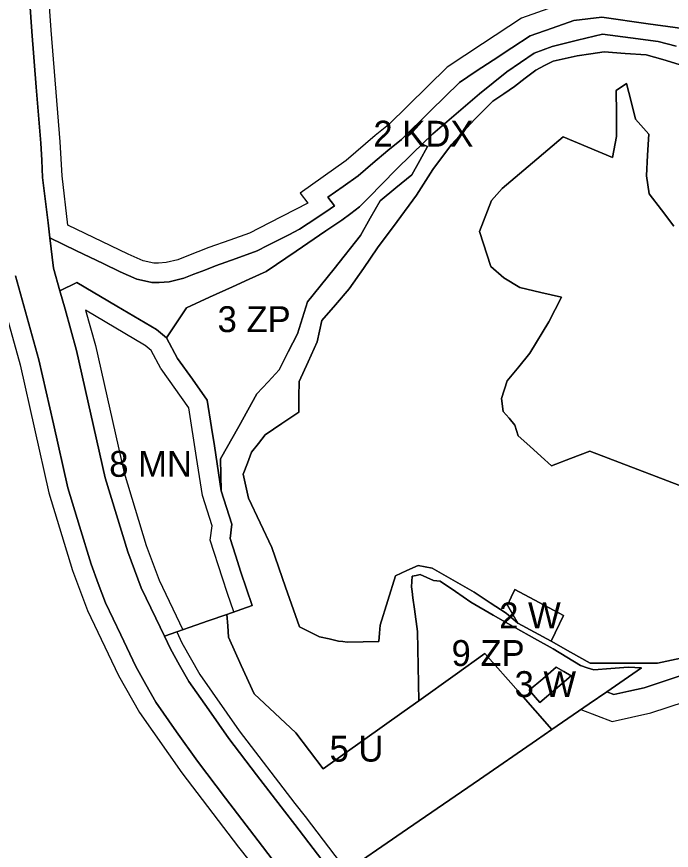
# Model space of a CAD drawing. Extents: x 7423691 to 7425475, y 5552085 to 5554331.
# Drawn here: x 7424385.3 to 7424587.5, y 5552663.9 to 5552921.5 of the extents above; entities that cross this region are included whole.
import ezdxf

# ---------------------------------------------------------------- set-up
doc = ezdxf.new("R2010")
doc.units = 0
for name, color, linetype in [('linia_zabudowy_nieprzekraczalna', 7, 'Continuous'), ('linie_rozgraniczajace', 7, 'Continuous'), ('oznaczenia_przeznaczen', 7, 'Continuous')]:
    doc.layers.add(name, color=color, linetype=linetype)

msp = doc.modelspace()

# ---------------------------------------------------------------- linework, layer by layer
at = {"layer": 'linia_zabudowy_nieprzekraczalna'}
for points in [[(7424556.1, 5552926.21), (7424541.26, 5552921.01), (7424529.19, 5552913.06), (7424518.25, 5552905.86), (7424500.12, 5552888.01), (7424496.07, 5552884.73), (7424487.09, 5552877.03), (7424472.85, 5552866.99), (7424475.26, 5552863.86), (7424463.35, 5552857.78), (7424457.15, 5552854.61), (7424451.09, 5552852.44), (7424444.67, 5552850.15), (7424437.81, 5552847.48), (7424435.04, 5552846.37), (7424431.41, 5552845.48), (7424429.06, 5552845.31), (7424427.69, 5552845.31), (7424424.32, 5552846.06), (7424419.75, 5552848.13), (7424401.1, 5552857.09), (7424399.27, 5552872.34), (7424398.71, 5552882.81), (7424395.91, 5552917.33), (7424395.1, 5552928.99)], [(7424378.95, 5552840.23), (7424386.33, 5552813.96), (7424395.24, 5552774.37), (7424402.55, 5552750.36), (7424407.19, 5552738.02), (7424416.77, 5552717.96), (7424423.18, 5552706.49), (7424436.27, 5552687.89), (7424453.78, 5552664.96), (7424456.99, 5552660.89), (7424481.21, 5552628.98), (7424487.16, 5552620.28), (7424504.05, 5552598.12), (7424504.53, 5552597.51), (7424504.36, 5552596.69), (7424479.58, 5552583.13), (7424397.48, 5552551.4), (7424333.75, 5552516.27)], [(7424452.41, 5552737.59), (7424450.45, 5552743.26), (7424448.87, 5552747.97), (7424445.05, 5552759.75), (7424445.63, 5552764.16), (7424442.63, 5552773.57), (7424440.82, 5552785.33), (7424438.46, 5552800.64), (7424429.89, 5552812.67), (7424429.82, 5552812.77), (7424426.81, 5552818.34), (7424426.79, 5552818.37), (7424424.99, 5552819.89), (7424424.97, 5552819.91), (7424424.8, 5552820.01), (7424406.53, 5552830.8), (7424409.61, 5552819.84), (7424418.46, 5552780.51), (7424425.28, 5552758.09), (7424429.29, 5552747.43), (7424436.6, 5552732.11)], [(7424434.7, 5552731.45), (7424436.32, 5552728.07), (7424441.82, 5552718.22), (7424454.01, 5552700.91), (7424471.16, 5552678.45), (7424474.39, 5552674.35), (7424487.13, 5552657.57)], [(7424559.55, 5552707.41), (7424569.21, 5552703.73), (7424581.21, 5552706.46), (7424602.66, 5552713.4), (7424603.78, 5552713.38), (7424612.4, 5552698.46), (7424624.81, 5552691.11), (7424646.93, 5552681.85), (7424649.5, 5552679.77), (7424651.53, 5552677.14), (7424652.42, 5552674.73), (7424652.99, 5552668.07), (7424648.05, 5552663.36)]]:
    msp.add_lwpolyline(points, dxfattribs=at)
at = {"layer": 'linie_rozgraniczajace'}
for points in [[(7424594.74, 5552917.28), (7424580.39, 5552919.29), (7424566.03, 5552921.29), (7424561.74, 5552920.81), (7424557.44, 5552920.32), (7424550.69, 5552917.96), (7424543.94, 5552915.59), (7424538.22, 5552911.82), (7424532.49, 5552908.05), (7424527.27, 5552904.61), (7424522.04, 5552901.17), (7424513.08, 5552892.35), (7424504.12, 5552883.53), (7424499.91, 5552880.12), (7424495.34, 5552876.21), (7424490.78, 5552872.29), (7424486.1, 5552869), (7424481.43, 5552865.7), (7424483.48, 5552863.05), (7424480.76, 5552861.23), (7424475.34, 5552857.6), (7424472.62, 5552855.78), (7424469.35, 5552854.1), (7424466.08, 5552852.43), (7424462.81, 5552850.76), (7424459.53, 5552849.09), (7424453.11, 5552846.79), (7424446.69, 5552844.5), (7424443.35, 5552843.19), (7424440.01, 5552841.89), (7424436.88, 5552840.65), (7424432.35, 5552839.53), (7424429.27, 5552839.31), (7424427.03, 5552839.31), (7424424.72, 5552839.83), (7424422.41, 5552840.34), (7424419.84, 5552841.5), (7424417.27, 5552842.66), (7424411.95, 5552845.22), (7424403.74, 5552849.17), (7424395.54, 5552853.11), (7424394.97, 5552857.79), (7424393.29, 5552871.83), (7424393.01, 5552877.12), (7424392.73, 5552882.41), (7424391.33, 5552899.64), (7424389.92, 5552916.88), (7424389.1, 5552928.86)], [(7424389.1, 5552928.86), (7424389.92, 5552916.88), (7424391.33, 5552899.64), (7424392.73, 5552882.41), (7424393.01, 5552877.12), (7424393.29, 5552871.83), (7424394.97, 5552857.79), (7424395.54, 5552853.11), (7424396.66, 5552843.76), (7424398.61, 5552836.8), (7424400.22, 5552831.07), (7424403.79, 5552818.37), (7424408.22, 5552798.67), (7424412.65, 5552778.98), (7424416.12, 5552767.57), (7424419.6, 5552756.16), (7424421.68, 5552750.62), (7424423.77, 5552745.08), (7424428.27, 5552735.65), (7424430.9, 5552730.13), (7424432.76, 5552726.23), (7424435.6, 5552721.16), (7424438.43, 5552716.08), (7424444.61, 5552707.31), (7424450.79, 5552698.54), (7424459.4, 5552687.27), (7424468, 5552676), (7424471.23, 5552671.9), (7424483.83, 5552655.3)], [(7424589, 5552912.34), (7424583.44, 5552913.81), (7424574.86, 5552914.96), (7424566.29, 5552916.1), (7424558.5, 5552914.16), (7424550.71, 5552912.21), (7424547.94, 5552911.23), (7424545.17, 5552910.24), (7424540.93, 5552907.32), (7424536.69, 5552904.41), (7424532.45, 5552901.04), (7424528.22, 5552897.67), (7424521.03, 5552891.5), (7424513.84, 5552885.32), (7424510.56, 5552882.1), (7424507.88, 5552879.48), (7424501.93, 5552873.65), (7424498.85, 5552870.47), (7424493.49, 5552865.01), (7424491.19, 5552862.72), (7424488.48, 5552860.64), (7424485.77, 5552858.57), (7424480.83, 5552855.26), (7424471.59, 5552848.98), (7424462.35, 5552842.7), (7424457.13, 5552840.34), (7424451.92, 5552837.98), (7424444.84, 5552834.77), (7424437.76, 5552831.56), (7424434.65, 5552826.89), (7424431.53, 5552822.21), (7424428.47, 5552824.81), (7424416.16, 5552832.08), (7424403.85, 5552839.35), (7424398.61, 5552836.8), (7424396.66, 5552843.76), (7424395.54, 5552853.11), (7424403.74, 5552849.17), (7424411.95, 5552845.22), (7424417.27, 5552842.66), (7424419.84, 5552841.5), (7424422.41, 5552840.34), (7424424.72, 5552839.83), (7424427.03, 5552839.31), (7424429.27, 5552839.31), (7424432.35, 5552839.53), (7424436.88, 5552840.65), (7424440.01, 5552841.89), (7424443.35, 5552843.19), (7424446.69, 5552844.5), (7424453.11, 5552846.79), (7424459.53, 5552849.09), (7424462.81, 5552850.76), (7424466.08, 5552852.43), (7424469.35, 5552854.1), (7424472.62, 5552855.78), (7424475.34, 5552857.6), (7424480.76, 5552861.23), (7424483.48, 5552863.05), (7424481.43, 5552865.7), (7424486.1, 5552869), (7424490.78, 5552872.29), (7424495.34, 5552876.21), (7424499.91, 5552880.12), (7424504.12, 5552883.53), (7424513.08, 5552892.35), (7424522.04, 5552901.17), (7424527.27, 5552904.61), (7424532.49, 5552908.05), (7424538.22, 5552911.82), (7424543.94, 5552915.59), (7424550.69, 5552917.96), (7424557.44, 5552920.32), (7424561.74, 5552920.81), (7424566.03, 5552921.29), (7424580.39, 5552919.29), (7424594.74, 5552917.28)], [(7424448.49, 5552774.95), (7424448.28, 5552784.84), (7424453.89, 5552794.92), (7424459.5, 5552805), (7424462.95, 5552808.69), (7424466.39, 5552812.38), (7424469.19, 5552817.95), (7424471.99, 5552823.52), (7424473.56, 5552828.45), (7424475.13, 5552833.39), (7424483.32, 5552843.62), (7424491.51, 5552853.86), (7424494.53, 5552859.2), (7424497.56, 5552864.54), (7424502.45, 5552868.6), (7424507.34, 5552872.66), (7424509.78, 5552877.03), (7424512.23, 5552881.4), (7424510.56, 5552882.1), (7424513.84, 5552885.32), (7424521.03, 5552891.5), (7424528.22, 5552897.67), (7424532.45, 5552901.04), (7424536.69, 5552904.41), (7424540.93, 5552907.32), (7424545.17, 5552910.24), (7424547.94, 5552911.23), (7424550.71, 5552912.21), (7424558.5, 5552914.16), (7424566.29, 5552916.1), (7424574.86, 5552914.96), (7424583.44, 5552913.81), (7424589, 5552912.34)], [(7424455.2, 5552780.11), (7424456.53, 5552783.5), (7424457.86, 5552786.89), (7424459.94, 5552789.58), (7424462.02, 5552792.26), (7424467.21, 5552795.78), (7424472.39, 5552799.29), (7424472.47, 5552804.02), (7424472.54, 5552808.75), (7424475.32, 5552814.87), (7424478.11, 5552821), (7424478.83, 5552824.32), (7424479.56, 5552827.64), (7424483.78, 5552832.5), (7424488, 5552837.37), (7424492.39, 5552843.72), (7424496.78, 5552850.07), (7424502.79, 5552858.2), (7424508.79, 5552866.33), (7424513.84, 5552874.24), (7424519.57, 5552882.02), (7424523.2, 5552885.89), (7424526.84, 5552889.76), (7424529.63, 5552892.56), (7424532.43, 5552895.35), (7424535.73, 5552897.64), (7424539.03, 5552899.93), (7424542.34, 5552902.43), (7424545.65, 5552904.93), (7424548.35, 5552906.35), (7424551.06, 5552907.77), (7424554.76, 5552908.54), (7424558.46, 5552909.32), (7424562.61, 5552909.94), (7424566.75, 5552910.56), (7424573.28, 5552910.13), (7424579.8, 5552909.69), (7424584.89, 5552908.19), (7424589.98, 5552906.68)], [(7424589.98, 5552906.68), (7424584.89, 5552908.19), (7424579.8, 5552909.69), (7424573.28, 5552910.13), (7424566.75, 5552910.56), (7424562.61, 5552909.94), (7424558.46, 5552909.32), (7424554.76, 5552908.54), (7424551.06, 5552907.77), (7424548.35, 5552906.35), (7424545.65, 5552904.93), (7424542.34, 5552902.43), (7424539.03, 5552899.93), (7424535.73, 5552897.64), (7424532.43, 5552895.35), (7424529.63, 5552892.56), (7424526.84, 5552889.76), (7424523.2, 5552885.89), (7424519.57, 5552882.02), (7424513.84, 5552874.24), (7424508.79, 5552866.33), (7424502.79, 5552858.2), (7424496.78, 5552850.07), (7424492.39, 5552843.72), (7424488, 5552837.37), (7424483.78, 5552832.5), (7424479.56, 5552827.64), (7424478.83, 5552824.32), (7424478.11, 5552821), (7424475.32, 5552814.87), (7424472.54, 5552808.75), (7424472.47, 5552804.02), (7424472.39, 5552799.29), (7424467.21, 5552795.78), (7424462.02, 5552792.26), (7424459.94, 5552789.58), (7424457.86, 5552786.89), (7424456.53, 5552783.5), (7424455.2, 5552780.11), (7424456.02, 5552776.41), (7424456.85, 5552772.71), (7424460.47, 5552765.09), (7424464.08, 5552757.46), (7424468.37, 5552745.21), (7424472.66, 5552732.95), (7424475.76, 5552731.44), (7424478.86, 5552729.93), (7424481.79, 5552729.24), (7424484.73, 5552728.55), (7424486.04, 5552728.42), (7424487.35, 5552728.29), (7424492.27, 5552728.37), (7424497.19, 5552728.46), (7424497.38, 5552730.99), (7424497.57, 5552733.52), (7424499.95, 5552741.15), (7424502.33, 5552748.78), (7424505.83, 5552750.36), (7424509.33, 5552751.93), (7424511.5, 5552751.53), (7424513.68, 5552751.13), (7424520.12, 5552747.41), (7424526.56, 5552743.69), (7424531.53, 5552740.45), (7424536.5, 5552737.21), (7424540.11, 5552734.12), (7424545.25, 5552731.33), (7424550.37, 5552728.52), (7424556.39, 5552725.13), (7424562.41, 5552721.74), (7424572.85, 5552721.74), (7424583.3, 5552721.73), (7424590.51, 5552723.27)], [(7424588.3, 5552856.8), (7424584.49, 5552861.75), (7424580.67, 5552866.69), (7424579.83, 5552872.26), (7424580.19, 5552878.71), (7424580.55, 5552885.16), (7424576.43, 5552889.79), (7424575.07, 5552895.29), (7424573.7, 5552900.79), (7424570.51, 5552898.62), (7424570.56, 5552891.52), (7424570.62, 5552884.42), (7424569.38, 5552878), (7424561.72, 5552881.16), (7424554.07, 5552884.33), (7424544.65, 5552876.36), (7424535.24, 5552868.38), (7424531.93, 5552864.65), (7424528.24, 5552855.09), (7424531.76, 5552844.32), (7424535.8, 5552840.76), (7424540.75, 5552837.82), (7424547.19, 5552836.3), (7424553.62, 5552834.77), (7424549.73, 5552827.15), (7424543.86, 5552817.56), (7424540.36, 5552813.32), (7424536.8, 5552809.01), (7424535.1, 5552803.51), (7424535.59, 5552799.51), (7424537.38, 5552797.4), (7424539.17, 5552795.3), (7424540.22, 5552792.03), (7424543.77, 5552788.81), (7424547.32, 5552785.59), (7424550.51, 5552782.7), (7424556.42, 5552784.96), (7424562.33, 5552787.23), (7424577.19, 5552781.58), (7424592.05, 5552775.93)], [(7424528.24, 5552855.09), (7424531.93, 5552864.65), (7424535.24, 5552868.38), (7424544.65, 5552876.36), (7424554.07, 5552884.33), (7424561.72, 5552881.16), (7424569.38, 5552878), (7424570.62, 5552884.42), (7424570.56, 5552891.52), (7424570.51, 5552898.62), (7424573.7, 5552900.79), (7424575.07, 5552895.29), (7424576.43, 5552889.79), (7424580.55, 5552885.16), (7424580.19, 5552878.71), (7424579.83, 5552872.26), (7424580.67, 5552866.69), (7424584.49, 5552861.75), (7424588.3, 5552856.8)], [(7424539.17, 5552795.3), (7424537.38, 5552797.4), (7424535.59, 5552799.51), (7424535.1, 5552803.51), (7424536.8, 5552809.01), (7424540.36, 5552813.32), (7424543.86, 5552817.56), (7424549.73, 5552827.15), (7424553.62, 5552834.77), (7424547.19, 5552836.3), (7424540.75, 5552837.82), (7424535.8, 5552840.76), (7424531.76, 5552844.32), (7424528.24, 5552855.09)], [(7424384.86, 5552841.41), (7424388.5, 5552828.42), (7424392.15, 5552815.43), (7424396.6, 5552795.67), (7424401.04, 5552775.91), (7424404.64, 5552764.1), (7424408.23, 5552752.3), (7424410.47, 5552746.33), (7424412.72, 5552740.37), (7424417.41, 5552730.54), (7424422.1, 5552720.71), (7424425.18, 5552715.2), (7424428.26, 5552709.69), (7424434.69, 5552700.56), (7424441.11, 5552691.44), (7424449.82, 5552680.04), (7424458.52, 5552668.64), (7424473.91, 5552648.52)], [(7424473.91, 5552648.52), (7424458.52, 5552668.64), (7424449.82, 5552680.04), (7424441.11, 5552691.44), (7424434.69, 5552700.56), (7424428.26, 5552709.69), (7424425.18, 5552715.2), (7424422.1, 5552720.71), (7424417.41, 5552730.54), (7424412.72, 5552740.37), (7424410.47, 5552746.33), (7424408.23, 5552752.3), (7424404.64, 5552764.1), (7424401.04, 5552775.91), (7424396.6, 5552795.67), (7424392.15, 5552815.43), (7424388.5, 5552828.42), (7424384.86, 5552841.41)], [(7424592.05, 5552775.93), (7424577.19, 5552781.58), (7424562.33, 5552787.23), (7424556.42, 5552784.96), (7424550.51, 5552782.7), (7424547.32, 5552785.59), (7424543.77, 5552788.81), (7424540.22, 5552792.03), (7424539.17, 5552795.3)], [(7424520.12, 5552747.41), (7424513.68, 5552751.13), (7424511.5, 5552751.53), (7424509.33, 5552751.93), (7424505.83, 5552750.36), (7424502.33, 5552748.78), (7424499.95, 5552741.15), (7424497.57, 5552733.52), (7424497.38, 5552730.99), (7424497.19, 5552728.46), (7424492.27, 5552728.37), (7424487.35, 5552728.29), (7424486.04, 5552728.42), (7424484.73, 5552728.55), (7424481.79, 5552729.24), (7424478.86, 5552729.93), (7424475.76, 5552731.44), (7424472.66, 5552732.95), (7424468.37, 5552745.21), (7424464.08, 5552757.46), (7424460.47, 5552765.09), (7424456.85, 5552772.71), (7424456.02, 5552776.41), (7424455.2, 5552780.11)], [(7424451.75, 5552764.71), (7424450.12, 5552769.83), (7424448.49, 5552774.95)], [(7424590.28, 5552717.8), (7424579.09, 5552714.18), (7424574.44, 5552713.12), (7424569.79, 5552712.06), (7424567.56, 5552712.92), (7424578.34, 5552720.33), (7424574.14, 5552720.49), (7424568.85, 5552720.09), (7424563.56, 5552719.7), (7424561.54, 5552720.37), (7424559.51, 5552721.04), (7424555.29, 5552723.6), (7424551.07, 5552726.16), (7424545.25, 5552729.4), (7424539.43, 5552732.65), (7424532.52, 5552736.64), (7424525.61, 5552740.64), (7424520.88, 5552743.87), (7424516.15, 5552747.1), (7424515.1, 5552747.2), (7424514.04, 5552747.3), (7424511.98, 5552748.21), (7424509.92, 5552749.12), (7424508.69, 5552748.88), (7424507.46, 5552748.64), (7424507.35, 5552747), (7424507.23, 5552745.37), (7424507.43, 5552743.89), (7424507.71, 5552741.9), (7424508.18, 5552738.44), (7424509.14, 5552731.51), (7424509.31, 5552720.84), (7424509.48, 5552710.16), (7424504.97, 5552706.95), (7424479.98, 5552689.16), (7424475.72, 5552694.72), (7424471.47, 5552700.27), (7424465.04, 5552706.28), (7424458.61, 5552712.3), (7424454.65, 5552721.03), (7424450.69, 5552729.76), (7424450.46, 5552733.3), (7424450.22, 5552736.84), (7424458.01, 5552739.54), (7424456.29, 5552744.69), (7424454.57, 5552749.85), (7424452.87, 5552755.08), (7424451.18, 5552760.31), (7424451.75, 5552764.71)], [(7424590.51, 5552723.27), (7424583.3, 5552721.73), (7424572.85, 5552721.74), (7424562.41, 5552721.74), (7424556.39, 5552725.13), (7424550.37, 5552728.52), (7424554.2, 5552736.52), (7424546.7, 5552740.51), (7424539.2, 5552744.5), (7424538.04, 5552742.11), (7424536.89, 5552739.71), (7424538.59, 5552736.75), (7424540.11, 5552734.12), (7424536.5, 5552737.21), (7424531.53, 5552740.45), (7424526.56, 5552743.69), (7424520.12, 5552747.41)], [(7424483.83, 5552655.3), (7424506.02, 5552670.56), (7424528.21, 5552685.83), (7424545.9, 5552698.02), (7424550.65, 5552701.28), (7424562.12, 5552709.17), (7424567.56, 5552712.92), (7424569.79, 5552712.06), (7424574.44, 5552713.12), (7424579.09, 5552714.18), (7424590.28, 5552717.8)]]:
    msp.add_lwpolyline(points, dxfattribs=at)
for points in [[(7424431.53, 5552822.21), (7424434.65, 5552826.89), (7424437.76, 5552831.56), (7424444.84, 5552834.77), (7424451.92, 5552837.98), (7424457.13, 5552840.34), (7424462.35, 5552842.7), (7424471.59, 5552848.98), (7424480.83, 5552855.26), (7424485.77, 5552858.57), (7424488.48, 5552860.64), (7424491.19, 5552862.72), (7424493.49, 5552865.01), (7424498.85, 5552870.47), (7424501.93, 5552873.65), (7424507.88, 5552879.48), (7424510.56, 5552882.1), (7424512.23, 5552881.4), (7424509.78, 5552877.03), (7424507.34, 5552872.66), (7424502.45, 5552868.6), (7424497.56, 5552864.54), (7424494.53, 5552859.2), (7424491.51, 5552853.86), (7424483.32, 5552843.62), (7424475.13, 5552833.39), (7424473.56, 5552828.45), (7424471.99, 5552823.52), (7424469.19, 5552817.95), (7424466.39, 5552812.38), (7424462.95, 5552808.69), (7424459.5, 5552805), (7424453.89, 5552794.92), (7424448.28, 5552784.84), (7424448.49, 5552774.95), (7424447.62, 5552780.59), (7424446.35, 5552788.86), (7424445.46, 5552794.6), (7424444.17, 5552802.96), (7424439.56, 5552809.44), (7424434.94, 5552815.92)], [(7424398.61, 5552836.8), (7424403.85, 5552839.35), (7424416.16, 5552832.08), (7424428.47, 5552824.81), (7424431.53, 5552822.21), (7424434.94, 5552815.92), (7424439.56, 5552809.44), (7424444.17, 5552802.96), (7424445.46, 5552794.6), (7424446.35, 5552788.86), (7424447.62, 5552780.59), (7424448.49, 5552774.95), (7424450.12, 5552769.83), (7424451.75, 5552764.71), (7424451.18, 5552760.31), (7424452.87, 5552755.08), (7424454.57, 5552749.85), (7424456.29, 5552744.69), (7424458.01, 5552739.54), (7424450.22, 5552736.84), (7424444.46, 5552734.84), (7424430.9, 5552730.13), (7424428.27, 5552735.65), (7424423.77, 5552745.08), (7424421.68, 5552750.62), (7424419.6, 5552756.16), (7424416.12, 5552767.57), (7424412.65, 5552778.98), (7424408.22, 5552798.67), (7424403.79, 5552818.37), (7424400.22, 5552831.07)], [(7424507.23, 5552745.37), (7424507.35, 5552747), (7424507.46, 5552748.64), (7424508.69, 5552748.88), (7424509.92, 5552749.12), (7424511.98, 5552748.21), (7424514.04, 5552747.3), (7424515.1, 5552747.2), (7424516.15, 5552747.1), (7424520.88, 5552743.87), (7424525.61, 5552740.64), (7424532.52, 5552736.64), (7424539.43, 5552732.65), (7424545.25, 5552729.4), (7424551.07, 5552726.16), (7424555.29, 5552723.6), (7424559.51, 5552721.04), (7424561.54, 5552720.37), (7424563.56, 5552719.7), (7424568.85, 5552720.09), (7424574.14, 5552720.49), (7424578.34, 5552720.33), (7424567.56, 5552712.92), (7424562.12, 5552709.17), (7424550.65, 5552701.28), (7424540.3, 5552713.01), (7424529.95, 5552724.74), (7424520.71, 5552718.15), (7424509.48, 5552710.16), (7424509.31, 5552720.84), (7424509.14, 5552731.51), (7424508.18, 5552738.44), (7424507.71, 5552741.9), (7424507.43, 5552743.89)], [(7424536.89, 5552739.71), (7424538.04, 5552742.11), (7424539.2, 5552744.5), (7424546.7, 5552740.51), (7424554.2, 5552736.52), (7424550.37, 5552728.52), (7424545.25, 5552731.33), (7424540.11, 5552734.12), (7424538.59, 5552736.75)], [(7424430.9, 5552730.13), (7424444.46, 5552734.84), (7424450.22, 5552736.84), (7424450.46, 5552733.3), (7424450.69, 5552729.76), (7424454.65, 5552721.03), (7424458.61, 5552712.3), (7424465.04, 5552706.28), (7424471.47, 5552700.27), (7424475.72, 5552694.72), (7424479.98, 5552689.16), (7424504.97, 5552706.95), (7424509.48, 5552710.16), (7424520.71, 5552718.15), (7424529.95, 5552724.74), (7424540.3, 5552713.01), (7424550.65, 5552701.28), (7424545.9, 5552698.02), (7424528.21, 5552685.83), (7424506.02, 5552670.56), (7424483.83, 5552655.3), (7424471.23, 5552671.9), (7424468, 5552676), (7424459.4, 5552687.27), (7424450.79, 5552698.54), (7424444.61, 5552707.31), (7424438.43, 5552716.08), (7424435.6, 5552721.16), (7424432.76, 5552726.23)], [(7424543.65, 5552713.42), (7424547.82, 5552716.95), (7424551.99, 5552720.48), (7424554.3, 5552719.16), (7424556.6, 5552717.83), (7424551.74, 5552713.72), (7424546.88, 5552709.6)], [(7424543.65, 5552713.42), (7424546.88, 5552709.6), (7424551.74, 5552713.72), (7424556.6, 5552717.83), (7424554.3, 5552719.16), (7424551.99, 5552720.48), (7424547.82, 5552716.95)]]:
    msp.add_lwpolyline(points, close=True, dxfattribs=at)

# ---------------------------------------------------------------- texts
at = {"layer": 'oznaczenia_przeznaczen'}
for s, p in [('2 KDX', (7424495.48, 5552881.32)), ('3 ZP', (7424447.34, 5552824.02)), ('8 MN', (7424413.86, 5552779.33)), ('2 W', (7424534.34, 5552732.52)), ('9 ZP', (7424519.62, 5552720.89)), ('3 W', (7424539.1, 5552711.29)), ('5 U', (7424481.93, 5552691.35))]:
    msp.add_text(s, height=8, dxfattribs=at).set_placement(p)

doc.saveas('drawing.dxf')
